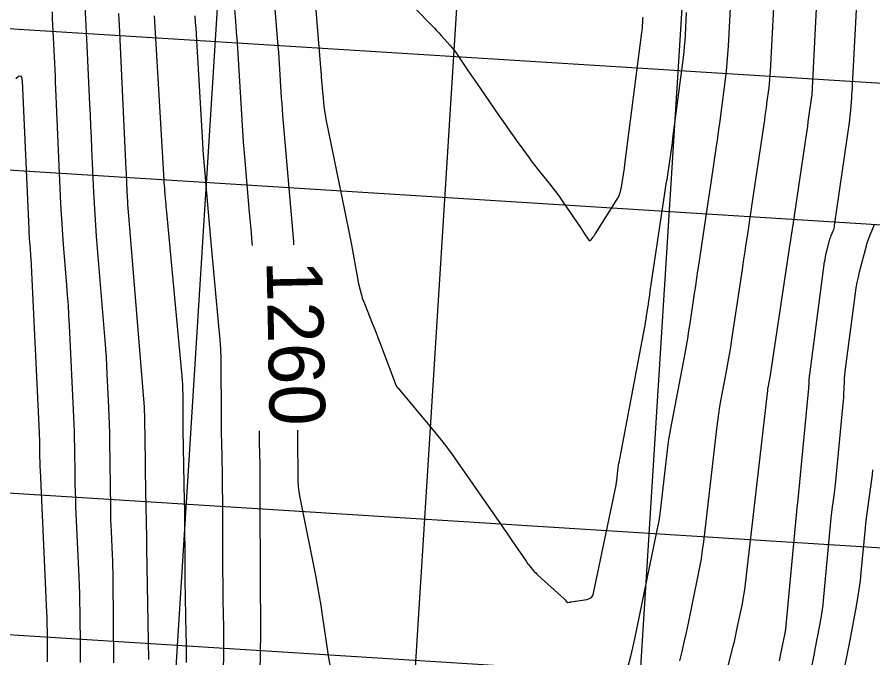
# Model space of a CAD drawing. Extents: x 658976 to 668721, y 639543 to 647196.
# Drawn here: x 661687.6 to 661779.9, y 641996.4 to 642065.5 of the extents above; entities that cross this region are included whole.
import ezdxf

# ---------------------------------------------------------------- set-up
doc = ezdxf.new("R2010")
doc.units = 0
for name, color, linetype in [('Ex_Contour Labels', 7, 'Continuous'), ('Ex_Major Contours', 7, 'Continuous'), ('Ex_Minor Contours', 7, 'Continuous'), ('R_Grid', 7, 'Continuous')]:
    doc.layers.add(name, color=color, linetype=linetype)

msp = doc.modelspace()

# ---------------------------------------------------------------- linework, layer by layer
at = {"layer": 'Ex_Major Contours'}
for points in [[(661717.486, 642040.926), (661717.457, 642041.255), (661717.42, 642041.682), (661716.292, 642054.9), (661716.241, 642055.518), (661716.195, 642056.136), (661716.152, 642056.754), (661716.114, 642057.373), (661715.969, 642059.847), (661715.931, 642060.466), (661715.889, 642061.084), (661715.844, 642061.702), (661715.795, 642062.32), (661714.904, 642073.092)], [(661764.547, 642067.137), (661764.304, 642062.338), (661764.249, 642061.434), (661764.177, 642060.532), (661764.087, 642059.631), (661763.98, 642058.732), (661763.516, 642055.139), (661763.398, 642054.241), (661763.276, 642053.343), (661763.149, 642052.446), (661763.018, 642051.55), (661762.431, 642047.614), (661762.289, 642046.659), (661762.147, 642045.704), (661762.004, 642044.75), (661761.861, 642043.795), (661761.133, 642038.928), (661761.012, 642038.117), (661760.891, 642037.306), (661760.77, 642036.494), (661760.649, 642035.683), (661760.165, 642032.437), (661760.04, 642031.627), (661759.907, 642030.817), (661759.766, 642030.009), (661759.618, 642029.203), (661758.078, 642021.092), (661757.974, 642020.515), (661757.88, 642019.936), (661757.797, 642019.356), (661757.724, 642018.774), (661756.962, 642012.179), (661756.897, 642011.664), (661756.82, 642011.15), (661756.731, 642010.639), (661756.631, 642010.129), (661754.196, 641998.423), (661754.095, 641997.947), (661753.988, 641997.471), (661753.877, 641996.997), (661753.76, 641996.524), (661753.285, 641994.633)], [(661698.045, 641995.849), (661697.979, 642004.951), (661697.971, 642005.584), (661697.958, 642006.217), (661697.938, 642006.85), (661697.912, 642007.482), (661697.796, 642010.012), (661697.77, 642010.644), (661697.749, 642011.277), (661697.733, 642011.91), (661697.723, 642012.543), (661697.639, 642019.738), (661697.624, 642020.645), (661697.601, 642021.552), (661697.569, 642022.458), (661697.53, 642023.364), (661697.356, 642026.989), (661697.308, 642027.895), (661697.253, 642028.801), (661697.191, 642029.706), (661697.121, 642030.61), (661696.205, 642041.819), (661696.114, 642043.004), (661696.033, 642044.191), (661695.964, 642045.378), (661695.906, 642046.565), (661695.697, 642051.317), (661695.644, 642052.505), (661695.59, 642053.693), (661695.535, 642054.881), (661695.479, 642056.069), (661695.179, 642062.353), (661695.111, 642063.797), (661695.044, 642065.24), (661694.979, 642066.684)], [(661721.385, 641995.635), (661721.26, 641996.387), (661720.565, 642000.998), (661720.406, 642002.016), (661720.235, 642003.033), (661720.053, 642004.048), (661719.86, 642005.061), (661718.165, 642013.677), (661718.06, 642014.282), (661717.985, 642014.891), (661717.939, 642015.503), (661717.922, 642016.117), (661717.908, 642019.703), (661717.908, 642019.758), (661717.907, 642019.813), (661717.907, 642019.869), (661717.906, 642019.924), (661717.902, 642020.146), (661717.901, 642020.202), (661717.9, 642020.257), (661717.899, 642020.313), (661717.899, 642020.368), (661717.896, 642020.93)], [(661776.937, 641995.578), (661777.114, 641996.486), (661777.289, 641997.394), (661777.461, 641998.302), (661778.144, 642001.937), (661778.304, 642002.847), (661778.443, 642003.76), (661778.561, 642004.676), (661778.658, 642005.596), (661779.104, 642010.372), (661779.156, 642010.898), (661779.216, 642011.423), (661779.283, 642011.948), (661779.357, 642012.471), (661779.666, 642014.564), (661779.74, 642015.088), (661779.807, 642015.612), (661779.867, 642016.137), (661779.92, 642016.663)]]:
    msp.add_lwpolyline(points, dxfattribs=at)
at = {"layer": 'Ex_Minor Contours'}
for points in [[(661718.967, 642076.793), (661720.389, 642059.592), (661720.393, 642059.541), (661720.397, 642059.49), (661720.4, 642059.438), (661720.403, 642059.387), (661720.415, 642059.182), (661720.418, 642059.13), (661720.422, 642059.079), (661720.426, 642059.028), (661720.43, 642058.977), (661720.658, 642056.3), (661720.705, 642055.838), (661720.765, 642055.378), (661720.838, 642054.92), (661720.925, 642054.463), (661722.986, 642044.458), (661723.165, 642043.577), (661723.341, 642042.694), (661723.512, 642041.81), (661723.678, 642040.926), (661724.46, 642036.725), (661724.577, 642036.175), (661724.719, 642035.633), (661724.889, 642035.099), (661725.085, 642034.572), (661725.923, 642032.48), (661726.131, 642031.957), (661726.336, 642031.433), (661726.539, 642030.907), (661726.739, 642030.381), (661728.5, 642025.715), (661728.503, 642025.708), (661728.506, 642025.702), (661728.509, 642025.696), (661728.513, 642025.69), (661728.529, 642025.666), (661728.533, 642025.66), (661728.537, 642025.655), (661728.542, 642025.649), (661728.546, 642025.644), (661728.647, 642025.531), (661728.665, 642025.511), (661728.683, 642025.49), (661728.701, 642025.469), (661728.718, 642025.448), (661732.638, 642020.749), (661733.288, 642019.953), (661733.921, 642019.142), (661734.536, 642018.318), (661735.133, 642017.481), (661739.84, 642010.723), (661740.13, 642010.306), (661740.418, 642009.888), (661740.704, 642009.469), (661740.989, 642009.049), (661742.509, 642006.796), (661742.602, 642006.661), (661742.7, 642006.53), (661742.8, 642006.401), (661742.905, 642006.275), (661743.33, 642005.776), (661743.438, 642005.653), (661743.55, 642005.534), (661743.666, 642005.418), (661743.785, 642005.307), (661746.629, 642002.737), (661746.665, 642002.703), (661746.697, 642002.668), (661746.728, 642002.63), (661746.756, 642002.59), (661746.866, 642002.423), (661746.895, 642002.39), (661746.928, 642002.367), (661746.967, 642002.356), (661747.01, 642002.357), (661747.196, 642002.38), (661747.242, 642002.386), (661747.288, 642002.393), (661747.334, 642002.399), (661747.38, 642002.407), (661749.077, 642002.682), (661749.346, 642002.761), (661749.555, 642002.902), (661749.706, 642003.105), (661749.797, 642003.37), (661752.218, 642015.011), (661752.241, 642015.125), (661752.261, 642015.239), (661752.278, 642015.353), (661752.292, 642015.468), (661752.462, 642016.939), (661752.478, 642017.068), (661752.497, 642017.198), (661752.518, 642017.327), (661752.541, 642017.456), (661755.279, 642031.879), (661755.341, 642032.212), (661755.399, 642032.547), (661755.454, 642032.882), (661755.506, 642033.217), (661755.706, 642034.56), (661755.756, 642034.896), (661755.806, 642035.232), (661755.856, 642035.568), (661755.906, 642035.903), (661757.49, 642046.488), (661757.564, 642046.981), (661757.637, 642047.474), (661757.711, 642047.968), (661757.784, 642048.461), (661758.078, 642050.433), (661758.15, 642050.926), (661758.22, 642051.42), (661758.287, 642051.913), (661758.352, 642052.408), (661759.475, 642061.1), (661759.547, 642061.708), (661759.608, 642062.316), (661759.656, 642062.926), (661759.693, 642063.537), (661759.817, 642065.982)], [(661762.519, 641988.38), (661764.842, 641997.628), (661764.972, 641998.158), (661765.097, 641998.689), (661765.216, 641999.222), (661765.33, 641999.756), (661765.775, 642001.895), (661765.88, 642002.43), (661765.973, 642002.968), (661766.054, 642003.508), (661766.123, 642004.049), (661768.536, 642024.932), (661768.567, 642025.176), (661768.601, 642025.419), (661768.641, 642025.661), (661768.684, 642025.903), (661768.868, 642026.869), (661768.912, 642027.111), (661768.954, 642027.353), (661768.994, 642027.595), (661769.032, 642027.838), (661771.033, 642041.275), (661771.047, 642041.364), (661771.06, 642041.453), (661771.073, 642041.542), (661771.086, 642041.631), (661771.14, 642041.986), (661771.153, 642042.075), (661771.166, 642042.164), (661771.179, 642042.253), (661771.193, 642042.342), (661772.679, 642052.324), (661772.748, 642052.785), (661772.815, 642053.246), (661772.882, 642053.707), (661772.949, 642054.168), (661773.341, 642056.896), (661773.344, 642056.915), (661773.346, 642056.935), (661773.348, 642056.954), (661773.349, 642056.974), (661773.355, 642057.052), (661773.357, 642057.071), (661773.358, 642057.091), (661773.359, 642057.11), (661773.36, 642057.13), (661774.174, 642072.818)], [(661713.019, 642040.834), (661712.991, 642041.136), (661712.892, 642042.221), (661712.796, 642043.306), (661712.703, 642044.391), (661712.153, 642050.824), (661712.056, 642052.008), (661711.967, 642053.192), (661711.886, 642054.378), (661711.813, 642055.563), (661711.535, 642060.308), (661711.462, 642061.494), (661711.382, 642062.679), (661711.295, 642063.864), (661711.201, 642065.048), (661710.808, 642069.8)], [(661769.362, 642069.998), (661768.837, 642059.619), (661768.811, 642059.182), (661768.776, 642058.745), (661768.733, 642058.309), (661768.681, 642057.874), (661768.456, 642056.135), (661768.399, 642055.7), (661768.34, 642055.266), (661768.278, 642054.832), (661768.215, 642054.398), (661766.826, 642045.073), (661766.741, 642044.504), (661766.656, 642043.934), (661766.571, 642043.365), (661766.486, 642042.795), (661766.146, 642040.518), (661766.06, 642039.949), (661765.975, 642039.379), (661765.89, 642038.81), (661765.806, 642038.24), (661764.681, 642030.695), (661764.557, 642029.89), (661764.425, 642029.086), (661764.285, 642028.283), (661764.137, 642027.482), (661763.53, 642024.28), (661763.385, 642023.479), (661763.255, 642022.675), (661763.14, 642021.869), (661763.039, 642021.061), (661761.632, 642008.89), (661761.516, 642007.975), (661761.379, 642007.062), (661761.222, 642006.153), (661761.044, 642005.247), (661759.978, 642000.121), (661759.76, 641999.1), (661759.532, 641998.083), (661759.294, 641997.067), (661759.045, 641996.054)], [(661769.837, 641996.048), (661769.921, 641996.431), (661770.001, 641996.815), (661770.447, 641999.044), (661770.455, 641999.083), (661770.462, 641999.122), (661770.47, 641999.161), (661770.477, 641999.201), (661770.507, 641999.357), (661770.514, 641999.396), (661770.52, 641999.436), (661770.525, 641999.475), (661770.529, 641999.515), (661771.747, 642012.562), (661771.755, 642012.637), (661771.763, 642012.711), (661771.772, 642012.785), (661771.783, 642012.859), (661771.827, 642013.154), (661771.837, 642013.228), (661771.846, 642013.302), (661771.855, 642013.377), (661771.863, 642013.451), (661773.003, 642025.451), (661773.014, 642025.575), (661773.023, 642025.7), (661773.031, 642025.825), (661773.037, 642025.95), (661773.058, 642026.45), (661773.064, 642026.575), (661773.073, 642026.7), (661773.086, 642026.824), (661773.101, 642026.949), (661774.711, 642039.081), (661774.75, 642039.342), (661774.796, 642039.602), (661774.851, 642039.86), (661774.913, 642040.116), (661775.24, 642041.375), (661775.278, 642041.512), (661775.321, 642041.647), (661775.369, 642041.78), (661775.421, 642041.912), (661775.641, 642042.437), (661775.691, 642042.569), (661775.733, 642042.704), (661775.766, 642042.841), (661775.791, 642042.98), (661777.389, 642054.104), (661777.434, 642054.436), (661777.473, 642054.769), (661777.506, 642055.103), (661777.534, 642055.437), (661777.632, 642056.775), (661777.656, 642057.11), (661777.678, 642057.445), (661777.698, 642057.779), (661777.716, 642058.114), (661778.28, 642068.98)], [(661694.453, 641995.882), (661694.453, 641996.62), (661694.45, 641997.358), (661694.421, 642001.419), (661694.409, 642002.342), (661694.389, 642003.264), (661694.36, 642004.187), (661694.323, 642005.109), (661693.977, 642012.663), (661693.943, 642013.472), (661693.916, 642014.281), (661693.896, 642015.091), (661693.883, 642015.9), (661693.845, 642019.14), (661693.832, 642019.949), (661693.812, 642020.759), (661693.784, 642021.568), (661693.748, 642022.377), (661693.275, 642032.207), (661693.218, 642033.301), (661693.152, 642034.395), (661693.076, 642035.488), (661692.992, 642036.58), (661692.635, 642040.948), (661692.551, 642042.041), (661692.477, 642043.134), (661692.413, 642044.227), (661692.36, 642045.322), (661691.813, 642057.718), (661691.782, 642058.41), (661691.75, 642059.102), (661691.718, 642059.794), (661691.686, 642060.486), (661691.554, 642063.253), (661691.521, 642063.945), (661691.489, 642064.637), (661691.458, 642065.329), (661691.427, 642066.021)], [(661730.594, 642066.353), (661732.375, 642064.537), (661732.623, 642064.282), (661732.868, 642064.024), (661733.11, 642063.763), (661733.348, 642063.499), (661734.298, 642062.439), (661734.531, 642062.17), (661734.753, 642061.893), (661734.966, 642061.609), (661735.168, 642061.317), (661736.239, 642059.712), (661736.484, 642059.346), (661736.731, 642058.982), (661736.979, 642058.618), (661737.229, 642058.256), (661739.031, 642055.653), (661739.264, 642055.316), (661739.498, 642054.98), (661739.733, 642054.644), (661739.967, 642054.308), (661740.907, 642052.964), (661741.143, 642052.629), (661741.38, 642052.295), (661741.62, 642051.962), (661741.861, 642051.631), (661742.831, 642050.306), (661743.075, 642049.976), (661743.323, 642049.649), (661743.574, 642049.325), (661743.829, 642049.003), (661745.211, 642047.28), (661745.523, 642046.883), (661745.827, 642046.48), (661746.123, 642046.072), (661746.411, 642045.657), (661748.44, 642042.677), (661748.632, 642042.396), (661748.824, 642042.114), (661749.29, 642041.429), (661749.345, 642041.369), (661749.4, 642041.349), (661749.456, 642041.367), (661749.513, 642041.426), (661749.74, 642041.738), (661749.796, 642041.817), (661749.851, 642041.897), (661749.904, 642041.977), (661749.957, 642042.058), (661752.329, 642045.834), (661752.501, 642046.141), (661752.639, 642046.46), (661752.743, 642046.793), (661752.812, 642047.138), (661753.118, 642049.182), (661753.132, 642049.276), (661753.156, 642049.433), (661753.16, 642049.464), (661753.165, 642049.496), (661753.169, 642049.527), (661753.173, 642049.559), (661755.011, 642063.796), (661755.029, 642063.948), (661755.045, 642064.1), (661755.057, 642064.252), (661755.066, 642064.405), (661755.097, 642065.016), (661755.106, 642065.168), (661755.116, 642065.321), (661755.129, 642065.473)], [(661701.821, 641996.207), (661701.616, 642008.211), (661701.614, 642008.303), (661701.613, 642008.395), (661701.612, 642008.486), (661701.612, 642008.578), (661701.61, 642008.944), (661701.61, 642009.036), (661701.609, 642009.127), (661701.608, 642009.219), (661701.606, 642009.31), (661701.513, 642014.365), (661701.499, 642015.163), (661701.486, 642015.961), (661701.475, 642016.759), (661701.465, 642017.557), (661701.411, 642022.129), (661701.409, 642022.237), (661701.406, 642022.345), (661701.403, 642022.453), (661701.398, 642022.561), (661701.377, 642022.992), (661701.371, 642023.099), (661701.365, 642023.207), (661701.357, 642023.315), (661701.349, 642023.422), (661699.628, 642044.488), (661699.599, 642044.867), (661699.573, 642045.247), (661699.551, 642045.626), (661699.533, 642046.006), (661699.466, 642047.525), (661699.449, 642047.905), (661699.431, 642048.285), (661699.414, 642048.665), (661699.396, 642049.045), (661698.654, 642064.595), (661698.625, 642065.219), (661698.596, 642065.843)], [(661702.412, 642065.595), (661703.448, 642047.879), (661703.466, 642047.591), (661703.485, 642047.304), (661703.507, 642047.016), (661703.531, 642046.729), (661703.629, 642045.58), (661703.653, 642045.292), (661703.679, 642045.005), (661703.705, 642044.718), (661703.731, 642044.431), (661705.387, 642026.757), (661705.427, 642026.279), (661705.456, 642025.8), (661705.474, 642025.321), (661705.482, 642024.841), (661705.491, 642022.921), (661705.495, 642022.441), (661705.5, 642021.961), (661705.506, 642021.481), (661705.514, 642021.001), (661705.658, 642013.198), (661705.67, 642012.499), (661705.679, 642011.799), (661705.686, 642011.099), (661705.69, 642010.399), (661705.7, 642007.599), (661705.704, 642006.899), (661705.711, 642006.199), (661705.719, 642005.499), (661705.73, 642004.799), (661705.829, 641998.979), (661705.842, 641997.949), (661705.847, 641996.919), (661705.842, 641995.889)], [(661706.787, 642065.599), (661706.84, 642064.937), (661706.888, 642064.274), (661706.933, 642063.612), (661706.974, 642062.949), (661707.619, 642051.909), (661707.671, 642051.078), (661707.728, 642050.248), (661707.79, 642049.418), (661707.858, 642048.589), (661708.141, 642045.271), (661708.213, 642044.442), (661708.286, 642043.613), (661708.361, 642042.784), (661708.438, 642041.955), (661709.396, 642031.734), (661709.481, 642030.703), (661709.543, 642029.671), (661709.583, 642028.638), (661709.599, 642027.603), (661709.622, 642023.124), (661709.628, 642022.258), (661709.637, 642021.393), (661709.648, 642020.528), (661709.663, 642019.662), (661709.727, 642016.201), (661709.741, 642015.336), (661709.752, 642014.47), (661709.761, 642013.605), (661709.765, 642012.739), (661709.794, 642005.44), (661709.798, 642004.722), (661709.804, 642004.003), (661709.813, 642003.285), (661709.824, 642002.567), (661709.873, 641999.694), (661709.882, 641998.976), (661709.885, 641998.257), (661709.882, 641997.539), (661709.873, 641996.821), (661709.683, 641985.739)], [(661687.477, 642058.842), (661687.765, 642059.101), (661687.977, 642059.146), (661688.113, 642058.977), (661688.173, 642058.594), (661688.878, 642042.598), (661688.891, 642042.337), (661688.906, 642042.076), (661688.924, 642041.815), (661688.944, 642041.554), (661689.029, 642040.512), (661689.049, 642040.251), (661689.067, 642039.99), (661689.083, 642039.729), (661689.097, 642039.468), (661690.003, 642020.636), (661690.018, 642020.301), (661690.029, 642019.966), (661690.038, 642019.631), (661690.043, 642019.296), (661690.059, 642017.955), (661690.064, 642017.62), (661690.072, 642017.285), (661690.084, 642016.95), (661690.097, 642016.615), (661690.8, 642001.278), (661690.82, 642000.795), (661690.835, 642000.313), (661690.846, 641999.829), (661690.851, 641999.346), (661690.865, 641997.414), (661690.868, 641996.93), (661690.867, 641996.447), (661690.864, 641995.964)], [(661770.835, 641983.041), (661773.602, 641996.858), (661773.696, 641997.331), (661773.788, 641997.804), (661773.879, 641998.278), (661773.969, 641998.751), (661774.325, 642000.647), (661774.409, 642001.122), (661774.481, 642001.598), (661774.543, 642002.076), (661774.593, 642002.555), (661775.425, 642011.467), (661775.455, 642011.767), (661775.49, 642012.067), (661775.528, 642012.366), (661775.57, 642012.665), (661775.746, 642013.859), (661775.788, 642014.158), (661775.827, 642014.457), (661775.861, 642014.757), (661775.891, 642015.057), (661776.686, 642023.42), (661776.717, 642023.764), (661776.742, 642024.109), (661776.764, 642024.454), (661776.78, 642024.799), (661776.837, 642026.18), (661776.855, 642026.525), (661776.881, 642026.869), (661776.914, 642027.213), (661776.956, 642027.555), (661778.037, 642035.7), (661778.123, 642036.281), (661778.227, 642036.859), (661778.348, 642037.434), (661778.487, 642038.005), (661779.215, 642040.808), (661779.3, 642041.113), (661779.396, 642041.414), (661779.502, 642041.711), (661779.619, 642042.005), (661780.107, 642043.173)], [(661713.595, 641980.025), (661713.921, 641999.042), (661713.924, 641999.319), (661713.926, 641999.595), (661713.924, 641999.872), (661713.921, 642000.148), (661713.902, 642001.254), (661713.898, 642001.531), (661713.894, 642001.808), (661713.892, 642002.084), (661713.89, 642002.361), (661713.837, 642016.221), (661713.834, 642016.681), (661713.83, 642017.142), (661713.824, 642017.602), (661713.816, 642018.063), (661713.782, 642019.904), (661713.774, 642020.365), (661713.768, 642020.825), (661713.768, 642020.845)]]:
    msp.add_lwpolyline(points, dxfattribs=at)
at = {"layer": 'R_Grid'}
for p, q in [((660411.57, 642144.332), (661908.62, 642050.311)), ((661699.611, 641913.142), (661712.147, 642112.749)), ((661749.513, 641910.008), (661762.049, 642109.615)), ((661721.233, 641846.42), (661736.903, 642095.929)), ((660408.436, 642094.431), (661905.486, 642000.41)), ((661633.966, 642052.295), (663131.016, 641958.274)), ((661630.832, 642002.394), (663127.882, 641908.372))]:
    msp.add_line(p, q, dxfattribs=at)

# ---------------------------------------------------------------- texts
at = {"layer": 'Ex_Contour Labels'}
msp.add_text('1260', height=6, rotation=271.1748, dxfattribs=at).set_placement((661714.521, 642039.198))

doc.saveas('drawing.dxf')
